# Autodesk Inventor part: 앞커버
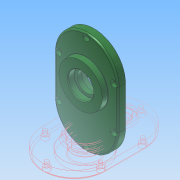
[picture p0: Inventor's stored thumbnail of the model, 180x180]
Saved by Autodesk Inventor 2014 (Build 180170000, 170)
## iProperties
Created: 2016-12
Part Number: 앞커버
Material: 알루미늄 6061
Document SubType Name: Modeling
Designer: mduedu
Density: 2.71 g/cm^3
Appearance: 매끄러움 - 짙은 산림 녹색
Mass: 264.836 g
Surface Area: 264.104 cm^2
Volume: 97.7255 cm^3
Author: mduedu
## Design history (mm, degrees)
sketch "스케치1"
  geometry: L1 (40, -25)-(40, 25); L2 (-40, 25)-(-40, -25); L3 (-40, -25)-(40, 25); L4 (40, -25)-(-40, 25); A1 r 40 centre (0, 25) between (40, 25) and (-40, 25); A2 r 40 centre (0, -25) between (-40, -25) and (40, -25); 1 further point
  constraints: 8 end point, 4 point on circle, 4 tangent, 2 centre point, 2 midpoint, 1 parallel, 1 vertical
  dimensions: "d0" = 130 dimension on A2 A1; "d2" = 80 distance between parallel lines of L1 L2
extrude "돌출1" new body sketch "스케치1" distance "d3" = 10; taper "d4" = 0 deg
sketch "스케치2"
  geometry: C1 r 21 at (0, 11); 1 further point
  constraints: 1 centre point, 1 vertical alignment
  dimensions: "d5" = 42 diameter of C1; "d7" = 11 distance of C1.centre point (0, 0)
extrude "돌출2" join sketch "스케치2" distance "d8" = 7; taper "d9" = 0 deg
sketch "스케치3"
  geometry: C1 r 15 at (0, -33.1); C2 r 21 at (0, 11) reference; 1 further point
  constraints: 1 centre point, 1 vertical alignment
  dimensions: "d10" = 30 diameter of C1; "d71" = 44.1 distance of C1.centre C2.centre
extrude "돌출3" join sketch "스케치3" distance "d12" = 7; taper "d13" = 0 deg
sketch "스케치4"
  geometry: C1 r 28 at (0, 11); A1 r 21 centre (0, 11) between (8.978, -7.984) and (-8.978, -7.984) reference; 1 further point
  constraints: 1 centre point, 1 coincident
  dimensions: "d14" = 56 diameter of C1
extrude "돌출4" join sketch "스케치4" distance "d15" = 7; taper "d16" = -5 deg
hole "구멍1" diameter "d19" = 35; stored, may be unused: countersink angle "d23" = 90 deg, drill point angle "d25" = 0 deg; dims "d17" = 10, "d18" = 10, "d20" = 6, "d21" = 4, "d22" = 2, "d24" = 10
hole "구멍2" diameter "d28" = 22; stored, may be unused: countersink angle "d32" = 90 deg, drill point angle "d34" = 0 deg; dims "d26" = 10, "d27" = 10, "d29" = 6, "d30" = 4, "d31" = 2, "d33" = 7
hole "구멍3" diameter "d37" = 19; stored, may be unused: countersink angle "d41" = 90 deg, drill point angle "d43" = 0 deg; dims "d35" = 10, "d36" = 10, "d38" = 6, "d39" = 4, "d40" = 2, "d42" = 1
hole "구멍4" diameter "d46" = 32; stored, may be unused: countersink angle "d50" = 90 deg, drill point angle "d52" = 0 deg; dims "d44" = 10, "d45" = 10, "d47" = 6, "d48" = 4, "d49" = 2, "d51" = 8
hole "구멍5" diameter "d55" = 25; stored, may be unused: countersink angle "d59" = 90 deg, drill point angle "d61" = 0 deg; dims "d53" = 10, "d54" = 10, "d56" = 6, "d57" = 4, "d58" = 2, "d60" = 8
fillet "모깎기1" dims "d62" = 0.3
fillet "모깎기2" dims "d63" = 2
chamfer "모따기1" distance "d64" = 1; stored, may be unused: second distance "d65" = 2, angle "d66" = 45 deg
fillet "모깎기4" dims "d68" = 2
fillet "모깎기5" dims "d69" = 0.3
fillet "모깎기6" dims "d70" = 2
sketch "스케치5"
  geometry: L1 (-40, 25)-(-40, -25) reference; L2 (40, -25)-(40, 25) reference; L3 (35, 25)-(35, -25); L4 (-35, -25)-(-35, 25); A1 r 40 centre (0, 25) between (40, 25) and (-40, 25) reference; A2 r 40 centre (0, -25) between (-40, -25) and (40, -25) reference; A3 r 35 centre (0, 25) between (35, 25) and (-35, 25); A4 r 35 centre (0, -25) between (-35, -25) and (35, -25); 2 further points
  constraints: 5 point on circle, 4 end point, 2 centre point, 1 vertical alignment, 3 other
  dimensions: "d72" = 5 distance between parallel lines of L2 L3
sketch "스케치7"
  geometry: 1 further point
hole "구멍7" sketch "스케치7" at (0, 60) diameter "d80" = 4.5; stored, may be unused: countersink angle "d84" = 90 deg, drill point angle "d86" = 0 deg; dims "d81" = 6, "d82" = 8, "d83" = 4.6, "d85" = 8
node "솔리드1"
pattern_linear "직사각형 패턴1"
